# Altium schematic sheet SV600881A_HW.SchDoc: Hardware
size 431 x 279 mm; Date: Not shown in title block; ApprovedBy: Not shown in title block; CheckedBy: Not shown in title block; Author: Not shown in title block; CompanyName: Not shown in title block; DrawnBy: KNielson; Engineer: Not shown in title block; Organization: Not shown in title block; Address1: Not shown in title block; Address2: Not shown in title block; Address3: Not shown in title block; Address4: Not shown in title block; DocumentNumber: 2; Revision: Use project parameter SCH_Rev; SheetNumber: 2; SheetTotal: 4; PageSetup: Record=PageOptions¦CenterHorizontal=True¦CenterVertical=True¦PrintScale=1.00¦XCorrection=1.00¦YCorrection=1.00¦PrintKind=0¦BorderSize=5000000¦LeftOffset=0¦BottomOffset=0¦Orientation=2¦PaperLength=1000¦PaperWidth=1000¦Scale=100¦PaperSource=15¦PrintQuality=600¦MediaType=1¦DitherType=10¦PaperKind=Letter¦PrintScaleMode=1
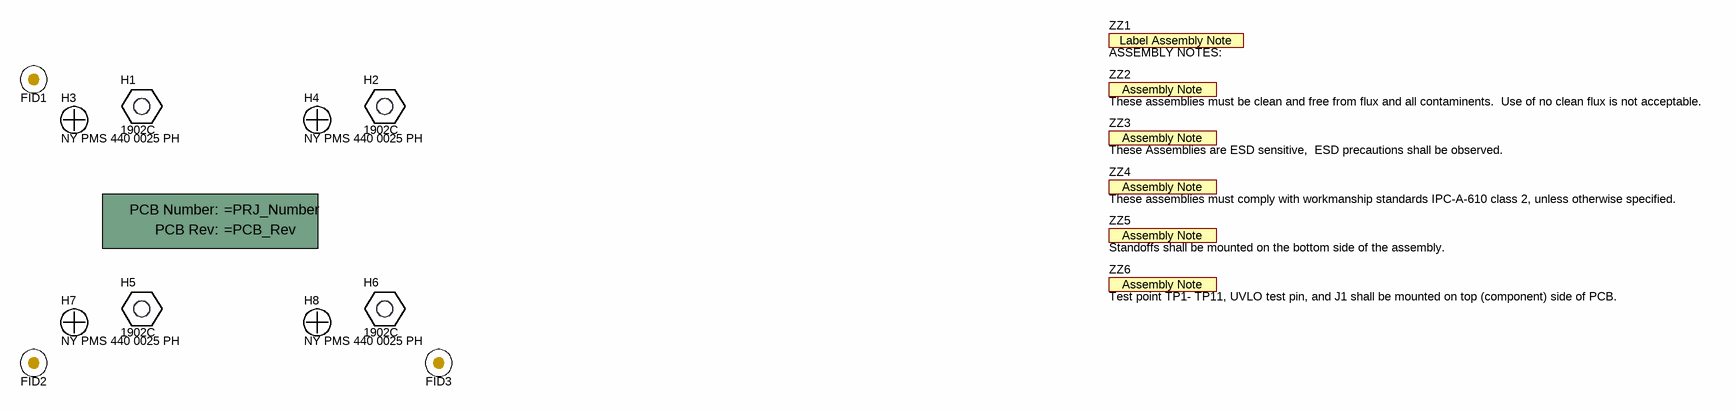
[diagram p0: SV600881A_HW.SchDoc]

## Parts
!PCB  Printed Circuit Board  (value not drawn)  (mechanical)
FID1  Fiducial  [Fiducial10-20]  (value not drawn)
FID2  Fiducial  [Fiducial10-20]  (value not drawn)
FID3  Fiducial  [Fiducial10-20]  (value not drawn)
H1  1902C  [Keystone_1902C]
H2  1902C  [Keystone_1902C]
H3  NY PMS 440 0025 PH  [NY PMS 440 0025 PH]
H4  NY PMS 440 0025 PH  [NY PMS 440 0025 PH]
H5  1902C  [Keystone_1902C]
H6  1902C  [Keystone_1902C]
H7  NY PMS 440 0025 PH  [NY PMS 440 0025 PH]
H8  NY PMS 440 0025 PH  [NY PMS 440 0025 PH]
ZZ1  ASSEMBLY NOTES:  [AssemblyNoteLabel]  (no BOM)
ZZ2  These assemblies must be clean and free from flux and all contaminents.  Use of no clean flux is not acceptable.  [AssemblyNote]  (no BOM)
ZZ3  These Assemblies are ESD sensitive,  ESD precautions shall be observed.  [AssemblyNote]  (no BOM)
ZZ4  These assemblies must comply with workmanship standards IPC-A-610 class 2, unless otherwise specified.  [AssemblyNote]  (no BOM)
ZZ5  Standoffs shall be mounted on the bottom side of the assembly.  [AssemblyNote]  (no BOM)
ZZ6  Test point TP1- TP11, UVLO test pin, and J1 shall be mounted on top (component) side of PCB.  [AssemblyNote]  (no BOM)

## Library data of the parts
!PCB = PCB: Manufacturer: Any; SymbolCreator: a0412235
FID1-FID3 = Fiducial: Fiducial mark.  There is nothing to buy or mount.; SymbolCreator: codlsc
H1 H2 H5 H6 = 1902C: Standoff, Hex, 0.5"L #4-40 Nylon; Manufacturer: Keystone; CompType: Hardware; U/M: EA
H3 H4 H7 H8 = NY PMS 440 0025 PH: Machine Screw, Round, #4-40 x 1/4, Nylon, Philips panhead; Manufacturer: B&F Fastener Supply; CompType: Hardware; SymbolCreator: codlsc; U/M: EA
ZZ1 = AssemblyNoteLabel: SymbolCreator: a0412235
ZZ2-ZZ6 = AssemblyNote: SymbolCreator: codlsc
